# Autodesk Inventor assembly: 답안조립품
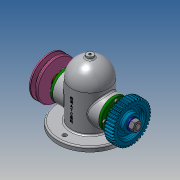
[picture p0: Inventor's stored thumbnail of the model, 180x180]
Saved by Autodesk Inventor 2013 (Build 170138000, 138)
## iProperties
Created: 2019-11
Part Number: 답안조립품
Document SubType Name: Assembly
Designer: Administrator
Author: Administrator
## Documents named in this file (14)
- C:\Users\Administrator\Desktop\답안조립품.iam
- C:\Users\Administrator\Desktop\본체.ipt
- C:\Users\Administrator\Desktop\491104V1052\V-벨트풀리.ipt
- V-벨트풀리.ipt
- C:\Users\Administrator\Desktop\491104V1052\너트 M12x1.25.ipt
- C:\Users\Administrator\Desktop\491104V1052\베어링 6203.ipt
- C:\Users\Administrator\Desktop\491104V1052\볼트 M4.ipt
- C:\Users\Administrator\Desktop\491104V1052\부시.ipt
- C:\Users\Administrator\Desktop\491104V1052\스퍼기어.ipt
- C:\Users\Administrator\Desktop\491104V1052\오일 실 26 38 8.ipt
- C:\Users\Administrator\Desktop\491104V1052\와셔 12x24.ipt
- C:\Users\Administrator\Desktop\491104V1052\축.ipt
- C:\Users\Administrator\Desktop\491104V1052\커버.ipt
- C:\Users\Administrator\Desktop\491104V1052\키 5x5x12.ipt
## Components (1 placed, 1 different names)
1. V-벨트풀리:1
